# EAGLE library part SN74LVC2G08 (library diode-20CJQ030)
Ti's SN74LVC2G08 DUAL 2-INPUT POSITIVE-AND GATE DESCRIPTION: The SN74LVC2G08 performs the Boolean function Y = A * B or Y =/( /A * /B ) in positive logic. This dual 2-input positive-AND gate is designed for 1.65-V to 5.5-V VCC operation. NanoStar and NanoFree package technology is a major breakthrough in IC packaging concepts, using the die as the package. This device is fully specified for partial-power-down applications using Ioff. The Ioff circuitry disables the outputs, preventing damaging current backflow through the device when it is powered down. Features: Available in the Texas Instruments NanoStar and NanoFree Packages Supports 5-V VCC Operation Inputs Accept Voltages to 5.5 V Max tpd of 4.7 ns at 3.3 V Low Power Consumption, 10-uA Max ICC ±24-mA Output Drive at 3.3 V Typical VOLP (Output Ground Bounce) 2 V at VCC = 3.3 V, TA = 25°C Ioff Supports Partial-Power-Down Mode Operation Latch-Up Performance Exceeds 100 mA Per JESD 78, Class II ESD Protection Exceeds JESD 22 - 2000-V Human-Body Model (A114-A) - 1000-V Charged-Device Model (C101) Please send any comments to: messi@users.sourceforge.net
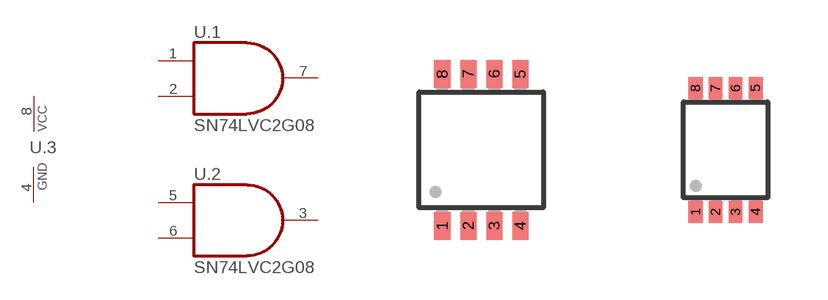
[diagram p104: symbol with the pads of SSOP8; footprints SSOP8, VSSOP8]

Designator prefix U; gates .1=7408 .2=7408 .3=PWR_GND

## SN74LVC2G08-DCT  [SSOP8]
1  .1:A  in
2  .1:B  in
3  .2:Y  out
4  .3:GND  pwr
5  .2:A  in
6  .2:B  in
7  .1:Y  out
8  .3:VCC  pwr

## SN74LVC2G08-DCU  [VSSOP8]
Pads as for SSOP8

## Footprint SSOP8 (pad centres in mm)
smd 0.4 x 0.7: 1 -0.975,-1.9; 2 -0.325,-1.9; 3 0.325,-1.9; 4 0.975,-1.9; 5 0.975,1.9; 6 0.325,1.9; 7 -0.325,1.9; 8 -0.975,1.9

## Footprint VSSOP8 (pad centres in mm)
smd 0.35 x 0.55: 1 -0.75,-1.55; 2 -0.25,-1.55; 3 0.25,-1.55; 4 0.75,-1.55; 5 0.75,1.55; 6 0.25,1.55; 7 -0.25,1.55; 8 -0.75,1.55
